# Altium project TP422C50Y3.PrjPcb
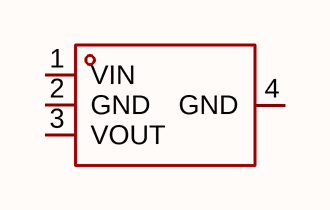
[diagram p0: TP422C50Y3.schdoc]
1 sheet, 1 parts. Net scope: global (net labels, ports and power ports of the same name join across sheets).

## Sheet TP422C50Y3.schdoc
size 127 x 101 mm

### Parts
U?  tp422c50y3  [SOT-223-4_L6.5-W3.5-P2.30-LS7.0-BR]  (value not drawn)

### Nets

Not connected (* = marked no-connect by the designer): U? 1(VIN) 2(GND) 3(VOUT) 4(GND)

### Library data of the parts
U? = tp422c50y3: 输出极性:正极;工作电压:36V;输出电压:5V;输出电流:300mA;电源纹波抑制比(PSRR):70dB;输出类型:固定;; Manufacturer: TECH PUBLIC(台舟); AddInBom: yes; ModelId: 925194bf9823436183a3e0b978a8d076; ModelName: SOT-223-4P_L6.5-W3.5-H1.6-LS7.0-P2.30; ModelTransform: 279.89794,255.905,0,180,0,0,-0.0005,-0.0005,0; Output Configuration: 正极; Voltage - Supply: 36V; Output Voltage: 5V; Output Current: 300mA; Power Supply Rejection Ratio (PSRR): 70dB; Voltage Dropout: 860mV@(300mA); standby current: 1.5uA; Output Type: 固定; Number of Outputs: 1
